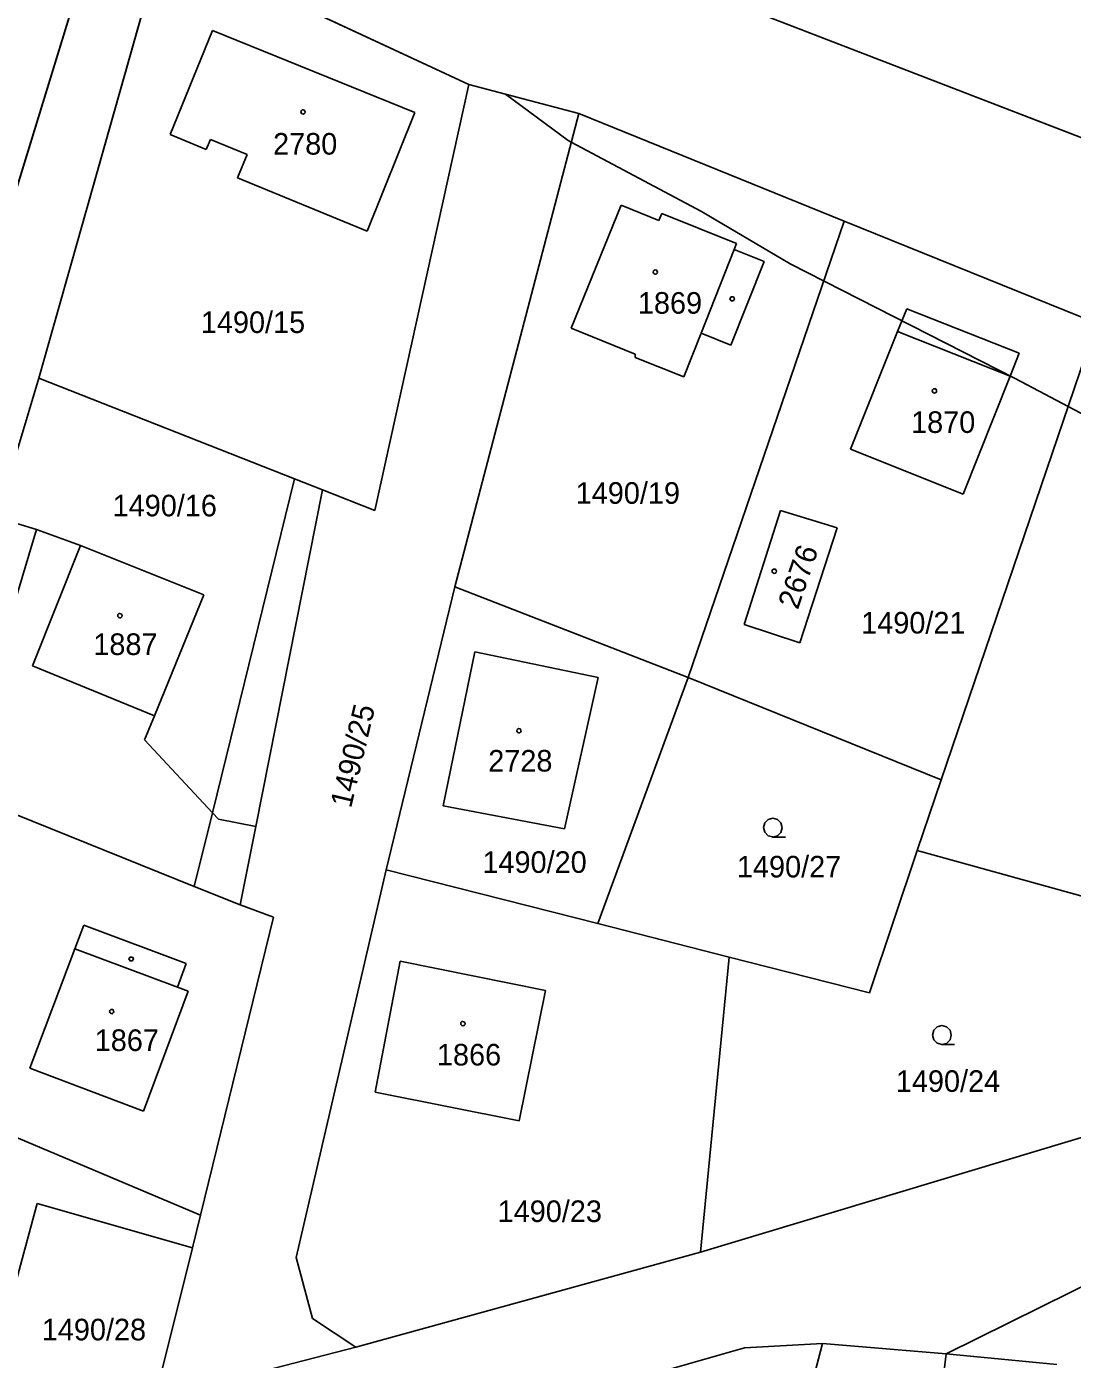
# Model space of a CAD drawing. Extents: x -779618 to -776429, y -1144546 to -1143350.
# Drawn here: x -777559.2 to -777476.8, y -1143853.5 to -1143748.5 of the extents above; entities that cross this region are included whole.
import ezdxf

# ---------------------------------------------------------------- set-up
doc = ezdxf.new("R2010")
doc.units = 0
for name, color, linetype in [('1', 7, 'Continuous'), ('11', 7, 'Continuous'), ('12', 7, 'Continuous'), ('2', 7, 'Continuous'), ('3', 7, 'Continuous'), ('4', 7, 'Continuous'), ('5', 7, 'Continuous')]:
    doc.layers.add(name, color=color, linetype=linetype)

msp = doc.modelspace()

# ---------------------------------------------------------------- linework, layer by layer
at = {"layer": '1'}
for p, q in [((-777556.08, -1143726.43), (-777462.27, -1143762.62)), ((-777572.48, -1143801.82), (-777554, -1143741.68)), ((-777548.54, -1143741.84), (-777558.25, -1143776.21)), ((-777524.39, -1143753.1), (-777548.54, -1143741.84)), ((-777547.92, -1143757.03), (-777544.58, -1143748.84)), ((-777544.58, -1143748.84), (-777528.63, -1143755.28)), ((-777531.8, -1143786.63), (-777524.39, -1143753.1)), ((-777515.73, -1143755.37), (-777524.39, -1143753.1)), ((-777528.63, -1143755.28), (-777532.39, -1143764.63)), ((-777525.48, -1143792.66), (-777515.73, -1143755.37)), ((-777494.83, -1143763.84), (-777515.73, -1143755.37)), ((-777545.07, -1143758.22), (-777547.92, -1143757.03)), ((-777544.73, -1143757.41), (-777545.07, -1143758.22)), ((-777541.85, -1143758.59), (-777544.73, -1143757.41)), ((-777542.62, -1143760.45), (-777541.85, -1143758.59)), ((-777532.39, -1143764.63), (-777542.62, -1143760.45)), ((-777516.33, -1143772.28), (-777512.38, -1143762.59)), ((-777512.38, -1143762.59), (-777509.41, -1143763.79)), ((-777509.41, -1143763.79), (-777509.19, -1143763.24)), ((-777509.19, -1143763.24), (-777503.3, -1143765.62)), ((-777507.11, -1143799.78), (-777494.83, -1143763.84)), ((-777494.83, -1143763.84), (-777474.95, -1143771.88)), ((-777503.3, -1143765.62), (-777503.49, -1143766.09)), ((-777503.49, -1143766.09), (-777501.12, -1143767.03)), ((-777501.12, -1143767.03), (-777503.74, -1143773.61)), ((-777489.89, -1143770.75), (-777490.61, -1143772.54)), ((-777481.04, -1143774.24), (-777489.89, -1143770.75)), ((-777511.29, -1143774.33), (-777516.33, -1143772.28)), ((-777506.08, -1143772.67), (-777507.44, -1143776.1)), ((-777503.74, -1143773.61), (-777506.08, -1143772.67)), ((-777490.61, -1143772.54), (-777494.32, -1143781.82)), ((-777487.19, -1143807.86), (-777474.95, -1143771.88)), ((-777511.29, -1143774.58), (-777511.29, -1143774.33)), ((-777507.44, -1143776.1), (-777511.29, -1143774.58)), ((-777481.75, -1143776.05), (-777481.04, -1143774.24)), ((-777558.25, -1143776.21), (-777561.56, -1143787.19)), ((-777558.25, -1143776.21), (-777538.11, -1143784.15)), ((-777485.45, -1143785.36), (-777481.75, -1143776.05)), ((-777494.32, -1143781.82), (-777485.45, -1143785.36)), ((-777544.59, -1143810.44), (-777538.11, -1143784.15)), ((-777538.11, -1143784.15), (-777535.92, -1143785.01)), ((-777531.8, -1143786.63), (-777535.92, -1143785.01)), ((-777561.56, -1143787.19), (-777558.44, -1143788.13)), ((-777502.7, -1143795.62), (-777499.84, -1143786.63)), ((-777499.84, -1143786.63), (-777495.36, -1143788)), ((-777558.44, -1143788.13), (-777554.99, -1143789.4)), ((-777495.36, -1143788), (-777498.3, -1143797.05)), ((-777554.99, -1143789.4), (-777545.26, -1143793.28)), ((-777545.26, -1143793.28), (-777549.16, -1143802.8)), ((-777530.89, -1143814.94), (-777525.48, -1143792.66)), ((-777525.48, -1143792.66), (-777507.11, -1143799.78)), ((-777498.3, -1143797.05), (-777502.7, -1143795.62)), ((-777526.42, -1143809.9), (-777523.92, -1143797.78)), ((-777523.92, -1143797.78), (-777514.2, -1143799.8)), ((-777514.2, -1143799.8), (-777516.86, -1143811.71)), ((-777514.23, -1143819.18), (-777507.11, -1143799.78)), ((-777487.19, -1143807.86), (-777507.11, -1143799.78)), ((-777549.16, -1143802.8), (-777549.94, -1143804.7)), ((-777549.94, -1143804.7), (-777544.59, -1143810.44)), ((-777567.68, -1143807.53), (-777546.02, -1143816.25)), ((-777489.08, -1143813.43), (-777487.19, -1143807.86)), ((-777546.02, -1143816.25), (-777544.59, -1143810.44)), ((-777516.86, -1143811.71), (-777526.42, -1143809.9)), ((-777492.83, -1143824.62), (-777489.08, -1143813.43)), ((-777489.08, -1143813.43), (-777468.25, -1143819.2)), ((-777537.99, -1143845.48), (-777530.89, -1143814.94)), ((-777514.23, -1143819.18), (-777530.89, -1143814.94)), ((-777546.02, -1143816.25), (-777542.4, -1143817.71)), ((-777539.77, -1143818.66), (-777542.4, -1143817.71)), ((-777545.52, -1143842.15), (-777539.77, -1143818.66)), ((-777554.72, -1143819.29), (-777555.42, -1143821.17)), ((-777546.65, -1143822.31), (-777554.72, -1143819.29)), ((-777503.88, -1143821.81), (-777514.23, -1143819.18)), ((-777555.42, -1143821.17), (-777558.97, -1143830.56)), ((-777506.15, -1143845.05), (-777503.88, -1143821.81)), ((-777503.88, -1143821.81), (-777492.83, -1143824.62)), ((-777547.35, -1143824.19), (-777546.65, -1143822.31)), ((-777531.78, -1143832.46), (-777529.79, -1143822.14)), ((-777529.79, -1143822.14), (-777518.36, -1143824.44)), ((-777550.02, -1143833.94), (-777546.49, -1143824.51)), ((-777546.49, -1143824.51), (-777547.35, -1143824.19)), ((-777518.36, -1143824.44), (-777520.42, -1143834.72)), ((-777558.97, -1143830.56), (-777550.02, -1143833.94)), ((-777520.42, -1143834.72), (-777531.78, -1143832.46)), ((-777470.29, -1143834.25), (-777506.15, -1143845.05)), ((-777449.55, -1143834.59), (-777486.78, -1143853.07)), ((-777562.42, -1143835.01), (-777545.52, -1143842.15)), ((-777563.57, -1143860.33), (-777558.4, -1143841.22)), ((-777558.4, -1143841.22), (-777546.16, -1143844.71)), ((-777546.16, -1143844.71), (-777545.52, -1143842.15)), ((-777546.16, -1143844.71), (-777548.69, -1143854.82)), ((-777533.28, -1143852.53), (-777506.15, -1143845.05)), ((-777536.71, -1143850.29), (-777537.99, -1143845.48)), ((-777533.28, -1143852.53), (-777536.71, -1143850.29)), ((-777496.53, -1143852.24), (-777502.67, -1143852.6)), ((-777496.53, -1143852.24), (-777501.62, -1143871.63)), ((-777486.78, -1143853.07), (-777496.53, -1143852.24)), ((-777551.16, -1143857.13), (-777533.28, -1143852.53)), ((-777508.91, -1143854.38), (-777502.67, -1143852.6)), ((-777489.3, -1143872.89), (-777486.78, -1143853.07)), ((-777486.78, -1143853.07), (-777478.06, -1143853.89))]:
    msp.add_line(p, q, dxfattribs=at)
at = {"layer": '11'}
for points in [[(-777835.96, -1143747.19), (-777823.97, -1143691.22), (-777815.03, -1143678.47), (-777780.89, -1143673.92), (-777725.33, -1143676.3), (-777700.17, -1143683.78), (-777654.9, -1143699.9), (-777586.96, -1143728.55), (-777571.45, -1143734.73), (-777568.02, -1143736.1), (-777554, -1143741.68), (-777592.84, -1143868.11), (-777585.29, -1143865.94), (-777580.95, -1143851.46), (-777575.32, -1143832.68), (-777574.4, -1143829.61), (-777567.68, -1143807.53), (-777564.44, -1143796.78), (-777561.56, -1143787.19), (-777558.25, -1143776.21), (-777548.54, -1143741.84), (-777524.39, -1143753.1), (-777521.49, -1143753.86)], [(-777215.44, -1143846.33), (-777291.06, -1143838.91), (-777294.79, -1143837.91), (-777307.07, -1143834.06), (-777326.59, -1143824.61), (-777334.23, -1143821.79), (-777375.94, -1143800.75), (-777415.86, -1143782.49), (-777462.27, -1143762.62), (-777554.92, -1143726.88)], [(-777521.49, -1143753.86), (-777516.57, -1143757.49), (-777516.32, -1143757.62), (-777506.06, -1143763.09), (-777499.08, -1143767.2), (-777481.34, -1143776.24), (-777460.86, -1143787.05), (-777440.34, -1143796.28), (-777418.3, -1143806.19)], [(-777521.49, -1143753.86), (-777515.73, -1143755.37), (-777494.83, -1143763.84), (-777474.95, -1143771.88), (-777437.2, -1143787.51), (-777405.54, -1143800.83), (-777387.68, -1143807.89), (-777356.13, -1143823.03), (-777352.24, -1143824.36), (-777344.73, -1143827.04), (-777336.84, -1143829.8), (-777324.83, -1143836.1), (-777303.85, -1143844.86), (-777292.27, -1143847.75), (-777289.53, -1143848.43), (-777281.88, -1143848.9), (-777167.58, -1143858.82), (-777035.36, -1143870.54), (-777014.02, -1143874.66), (-776998.39, -1143882.22), (-776992.99, -1143881.07), (-776972.79, -1143876.78), (-776970.83, -1143876.37), (-776959.34, -1143880.62)]]:
    msp.add_lwpolyline(points, dxfattribs=at)
at = {"layer": '12'}
for p, q in [((-777547.92, -1143757.03), (-777544.58, -1143748.84)), ((-777544.58, -1143748.84), (-777528.63, -1143755.28)), ((-777528.63, -1143755.28), (-777532.39, -1143764.63)), ((-777545.07, -1143758.22), (-777547.92, -1143757.03)), ((-777544.73, -1143757.41), (-777545.07, -1143758.22)), ((-777541.85, -1143758.59), (-777544.73, -1143757.41)), ((-777542.62, -1143760.45), (-777541.85, -1143758.59)), ((-777532.39, -1143764.63), (-777542.62, -1143760.45)), ((-777516.33, -1143772.28), (-777512.38, -1143762.59)), ((-777512.38, -1143762.59), (-777509.41, -1143763.79)), ((-777509.41, -1143763.79), (-777509.19, -1143763.24)), ((-777509.19, -1143763.24), (-777503.3, -1143765.62)), ((-777506.08, -1143772.67), (-777503.49, -1143766.09)), ((-777503.3, -1143765.62), (-777503.49, -1143766.09)), ((-777511.29, -1143774.33), (-777516.33, -1143772.28)), ((-777506.08, -1143772.67), (-777507.44, -1143776.1)), ((-777490.61, -1143772.54), (-777494.32, -1143781.82)), ((-777490.61, -1143772.54), (-777481.75, -1143776.05)), ((-777511.29, -1143774.58), (-777511.29, -1143774.33)), ((-777507.44, -1143776.1), (-777511.29, -1143774.58)), ((-777485.45, -1143785.36), (-777481.75, -1143776.05)), ((-777494.32, -1143781.82), (-777485.45, -1143785.36)), ((-777502.7, -1143795.62), (-777499.84, -1143786.63)), ((-777499.84, -1143786.63), (-777495.36, -1143788)), ((-777495.36, -1143788), (-777498.3, -1143797.05)), ((-777554.99, -1143789.4), (-777558.75, -1143798.87)), ((-777554.99, -1143789.4), (-777545.26, -1143793.28)), ((-777545.26, -1143793.28), (-777549.16, -1143802.8)), ((-777498.3, -1143797.05), (-777502.7, -1143795.62)), ((-777526.42, -1143809.9), (-777523.92, -1143797.78)), ((-777523.92, -1143797.78), (-777514.2, -1143799.8)), ((-777558.75, -1143798.87), (-777549.16, -1143802.8)), ((-777514.2, -1143799.8), (-777516.86, -1143811.71)), ((-777516.86, -1143811.71), (-777526.42, -1143809.9)), ((-777555.42, -1143821.17), (-777558.97, -1143830.56)), ((-777555.42, -1143821.17), (-777547.35, -1143824.19)), ((-777531.78, -1143832.46), (-777529.79, -1143822.14)), ((-777529.79, -1143822.14), (-777518.36, -1143824.44)), ((-777550.02, -1143833.94), (-777546.49, -1143824.51)), ((-777546.49, -1143824.51), (-777547.35, -1143824.19)), ((-777518.36, -1143824.44), (-777520.42, -1143834.72)), ((-777558.97, -1143830.56), (-777550.02, -1143833.94)), ((-777520.42, -1143834.72), (-777531.78, -1143832.46))]:
    msp.add_line(p, q, dxfattribs=at)
at = {"layer": '3'}
for points in [[(-777500.43, -1143812.35), (-777500.81, -1143812.25), (-777501.08, -1143811.98), (-777501.18, -1143811.61), (-777501.08, -1143811.24), (-777500.81, -1143810.97), (-777500.44, -1143810.87), (-777500.07, -1143810.97), (-777499.8, -1143811.24), (-777499.7, -1143811.62), (-777499.8, -1143812), (-777500.07, -1143812.27), (-777500.45, -1143812.37), (-777499.45, -1143812.37)], [(-777487.11, -1143828.69), (-777487.49, -1143828.59), (-777487.76, -1143828.32), (-777487.86, -1143827.95), (-777487.76, -1143827.58), (-777487.49, -1143827.31), (-777487.12, -1143827.21), (-777486.75, -1143827.31), (-777486.48, -1143827.58), (-777486.38, -1143827.96), (-777486.48, -1143828.34), (-777486.75, -1143828.61), (-777487.13, -1143828.71), (-777486.13, -1143828.71)]]:
    msp.add_lwpolyline(points, dxfattribs=at)
at = {"layer": '4'}
for p, q in [((-777506.08, -1143772.67), (-777503.49, -1143766.09)), ((-777490.61, -1143772.54), (-777481.75, -1143776.05)), ((-777541.16, -1143811.54), (-777535.92, -1143785.01)), ((-777561.33, -1143797.71), (-777558.44, -1143788.13)), ((-777554.99, -1143789.4), (-777558.75, -1143798.87)), ((-777558.75, -1143798.87), (-777549.16, -1143802.8)), ((-777544.59, -1143810.44), (-777544.1, -1143810.96)), ((-777544.1, -1143810.96), (-777541.16, -1143811.54)), ((-777542.4, -1143817.71), (-777541.16, -1143811.54)), ((-777555.42, -1143821.17), (-777547.35, -1143824.19))]:
    msp.add_line(p, q, dxfattribs=at)
at = {"layer": '5'}
for points in [[(-777537.45, -1143755.08), (-777537.35, -1143755.1), (-777537.3, -1143755.19), (-777537.28, -1143755.25), (-777537.3, -1143755.34), (-777537.38, -1143755.41), (-777537.45, -1143755.42), (-777537.54, -1143755.39), (-777537.6, -1143755.33), (-777537.62, -1143755.25), (-777537.6, -1143755.16), (-777537.52, -1143755.09)], [(-777509.7, -1143767.69), (-777509.6, -1143767.71), (-777509.55, -1143767.8), (-777509.53, -1143767.86), (-777509.55, -1143767.95), (-777509.63, -1143768.02), (-777509.7, -1143768.03), (-777509.79, -1143768), (-777509.85, -1143767.94), (-777509.87, -1143767.86), (-777509.85, -1143767.77), (-777509.77, -1143767.7)], [(-777503.55, -1143769.82), (-777503.46, -1143769.97), (-777503.55, -1143770.12), (-777503.73, -1143770.12), (-777503.82, -1143769.97), (-777503.73, -1143769.82)], [(-777487.71, -1143777.05), (-777487.61, -1143777.07), (-777487.56, -1143777.16), (-777487.54, -1143777.22), (-777487.56, -1143777.31), (-777487.64, -1143777.38), (-777487.71, -1143777.39), (-777487.8, -1143777.36), (-777487.86, -1143777.3), (-777487.88, -1143777.22), (-777487.86, -1143777.13), (-777487.78, -1143777.06)], [(-777500.33, -1143791.25), (-777500.23, -1143791.27), (-777500.18, -1143791.36), (-777500.16, -1143791.42), (-777500.18, -1143791.51), (-777500.26, -1143791.58), (-777500.33, -1143791.59), (-777500.42, -1143791.56), (-777500.48, -1143791.5), (-777500.5, -1143791.42), (-777500.48, -1143791.33), (-777500.4, -1143791.26)], [(-777551.88, -1143794.75), (-777551.78, -1143794.77), (-777551.73, -1143794.86), (-777551.71, -1143794.92), (-777551.73, -1143795.01), (-777551.81, -1143795.08), (-777551.88, -1143795.09), (-777551.97, -1143795.06), (-777552.03, -1143795), (-777552.05, -1143794.92), (-777552.03, -1143794.83), (-777551.95, -1143794.76)], [(-777520.44, -1143803.82), (-777520.34, -1143803.84), (-777520.29, -1143803.93), (-777520.27, -1143803.99), (-777520.29, -1143804.08), (-777520.37, -1143804.15), (-777520.44, -1143804.16), (-777520.53, -1143804.13), (-777520.59, -1143804.07), (-777520.61, -1143803.99), (-777520.59, -1143803.9), (-777520.51, -1143803.83)], [(-777550.89, -1143821.81), (-777550.8, -1143821.96), (-777550.89, -1143822.11), (-777551.07, -1143822.11), (-777551.16, -1143821.96), (-777551.07, -1143821.81)], [(-777552.52, -1143825.93), (-777552.42, -1143825.95), (-777552.37, -1143826.04), (-777552.35, -1143826.1), (-777552.37, -1143826.19), (-777552.45, -1143826.26), (-777552.52, -1143826.27), (-777552.61, -1143826.24), (-777552.67, -1143826.18), (-777552.69, -1143826.1), (-777552.67, -1143826.01), (-777552.59, -1143825.94)], [(-777524.86, -1143826.88), (-777524.76, -1143826.9), (-777524.71, -1143826.99), (-777524.69, -1143827.05), (-777524.71, -1143827.14), (-777524.79, -1143827.21), (-777524.86, -1143827.22), (-777524.95, -1143827.19), (-777525.01, -1143827.13), (-777525.03, -1143827.05), (-777525.01, -1143826.96), (-777524.93, -1143826.89)]]:
    msp.add_lwpolyline(points, close=True, dxfattribs=at)

# ---------------------------------------------------------------- texts
at = {"layer": '2'}
for s, p in [('2780', (-777539.81, -1143758.61)), ('1869', (-777511.07, -1143771.14)), ('1490/15', (-777545.5, -1143772.66)), ('1870', (-777489.55, -1143780.53)), ('1490/19', (-777515.97, -1143786.11)), ('1490/16', (-777552.45, -1143787.1)), ('1490/21', (-777493.48, -1143796.33)), ('1887', (-777553.97, -1143798.02)), ('2728', (-777522.86, -1143807.2)), ('1490/20', (-777523.32, -1143815.18)), ('1490/27', (-777503.27, -1143815.54)), ('1867', (-777553.86, -1143829.21)), ('1866', (-777526.9, -1143830.35)), ('1490/24', (-777490.75, -1143832.43)), ('1490/23', (-777522.12, -1143842.68)), ('1490/28', (-777558.03, -1143852))]:
    msp.add_text(s, height=1.7, dxfattribs=at).set_placement(p)
for s, rotation, p in [('2676', 71.1041, (-777498.47, -1143794.51)), ('1490/25', 76.5472, (-777533.67, -1143810.14))]:
    msp.add_text(s, height=1.7, rotation=rotation, dxfattribs=at).set_placement(p)

doc.saveas('drawing.dxf')
